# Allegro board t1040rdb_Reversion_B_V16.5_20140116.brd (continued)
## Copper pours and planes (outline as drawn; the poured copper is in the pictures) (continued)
(no net) on TOP: 52.7,56.13 52.45,56.39 52.45,60.32 50.93,61.85 50.93,75.18 50.29,75.82 40.77,75.82 40.39,76.2 40.39,79.76 39.88,80.26 37.08,80.26 36.58,79.76 36.58,76.2 35.56,75.18 30.1,75.18 29.84,75.44 29.84,77.6 30.61,78.36 32.38,78.36 35.31,81.28 53.47,81.28 53.98,80.77 53.98,80.01 54.61,79.38 54.61,77.98 55.37,77.22 58.17,77.22 59.56,75.82 61.21,75.82 61.47,76.07 61.47,78.74 61.59,78.87 64.01,78.87 64.77,78.11 67.31,78.11 67.95,78.74 67.95,82.17 67.44,82.68 64.77,82.68 64.39,83.06 64.39,83.82 63.88,84.33 63.5,84.33 63.37,84.45 63.37,85.34 63.5,85.47 68.96,85.47 69.98,84.45 69.98,74.93 69.09,74.04 55.88,74.04 55.37,73.53 55.37,62.1 57.02,60.45 57.02,56.39 56.77,56.13
(no net) on TOP: 205.49,131.83 208.03,131.83 208.41,132.21 208.41,140.21 208.03,140.59 204.98,140.59 202.95,138.56 202.95,133.86 203.2,133.6 204.72,133.6 205.1,133.22 205.1,132.21
(no net) on TOP: 29.72,110.36 27.43,110.36 26.8,111 24,111 23.88,111.12 23.88,112.52 24,112.65 26.67,112.65 27.94,113.92 29.72,113.92 29.97,113.67 29.97,110.62
(no net) on TOP: 70.48,85.09 70.48,77.09 70.87,76.71 75.57,76.71 75.95,77.09 75.95,80.77 75.69,81.03 75.31,81.03 74.99,81.34 74.99,82.55 74.04,83.5 74.04,86.36 73.79,86.61 72.01,86.61
(no net) on BOTTOM: 23.11,99.57 22.48,99.57 22.35,99.7 22.35,100.33 22.1,100.58 21.59,100.58 21.46,100.71 21.46,103 21.59,103.12 22.99,103.12 23.24,102.87 23.24,99.7
(no net) on BOTTOM: 73.79,76.33 73.79,84.96 73.15,85.6 71.12,85.6 70.87,85.34 70.87,76.33 71.12,76.07 73.53,76.07
(no net) on BOTTOM: 218.31,138.68 218.95,138.68 219.07,138.56 219.07,137.92 219.33,137.67 219.84,137.67 219.96,137.54 219.96,135.25 219.84,135.13 218.44,135.13 218.19,135.38 218.19,138.56
(no net) on BOTTOM: 187.45,74.17 187.71,74.42 187.71,83.82 187.45,84.07 185.29,84.07 183.26,82.04 183.26,74.68 183.77,74.17
(no net) on BOTTOM: 60.58,78.61 59.94,78.61 59.82,78.74 59.82,79.38 59.56,79.63 59.05,79.63 58.93,79.76 58.93,82.04 59.05,82.17 60.45,82.17 60.71,81.92 60.71,78.74
(no net) on BOTTOM: 23.11,88.77 22.48,88.77 22.35,88.9 22.35,89.54 22.1,89.79 21.59,89.79 21.46,89.92 21.46,92.2 21.59,92.33 22.99,92.33 23.24,92.08 23.24,88.9
(no net) on BOTTOM: 61.21,82.17 61.21,81.28 61.47,81.03 65.28,81.03 65.53,81.28 65.53,84.33 64.39,85.47 61.47,85.47 61.09,85.85 59.18,85.85 58.93,85.6 58.93,83.06 59.31,82.68 60.71,82.68
(no net) on BOTTOM: 36.32,108.08 36.32,117.48 36.07,117.73 33.66,117.73 33.4,117.48 33.4,108.08 33.66,107.82 36.07,107.82
(no net) on BOTTOM: 23.75,113.92 23.75,113.03 24,112.78 27.81,112.78 28.07,113.03 28.07,116.08 26.92,117.22 24,117.22 23.62,117.6 21.72,117.6 21.46,117.35 21.46,114.81 21.84,114.43 23.24,114.43
(no net) on BOTTOM: 197.99,81.53 198.63,81.53 198.75,81.41 198.75,80.77 199.01,80.52 199.52,80.52 199.64,80.39 199.64,78.11 199.52,77.98 198.12,77.98 197.87,78.23 197.87,81.41
(no net) on BOTTOM: 188.47,74.17 188.21,74.42 188.21,86.74 188.72,87.25 188.72,92.46 189.36,93.09 195.71,93.09 197.29,91.5 197.29,85.28 197.23,85.22 197.23,80.14 196.72,79.63 193.04,79.63 192.53,79.12 192.53,74.42 192.28,74.17
(no net) on BOTTOM: 23.11,110.36 22.48,110.36 22.35,110.49 22.35,111.12 22.1,111.38 21.59,111.38 21.46,111.51 21.46,113.79 21.59,113.92 22.99,113.92 23.24,113.67 23.24,110.49
(no net) on BOTTOM: 197.1,74.68 194.18,74.68 193.04,75.82 193.04,78.87 193.29,79.12 197.1,79.12 197.36,78.87 197.36,77.98 197.87,77.47 199.26,77.47 199.64,77.09 199.64,76.96 200.91,76.96 203.71,74.17 208.28,74.17 213.87,79.76 213.87,90.93 214.25,91.31 222.12,91.31 227.84,87.26 227.84,78.74 225.17,76.07 216.03,76.07 211.96,72.01 199.77,72.01 ; 1 cut-out
(no net) on BOTTOM: 36.32,97.28 36.32,106.68 36.07,106.93 33.66,106.93 33.4,106.68 33.4,97.28 33.66,97.03 36.07,97.03
(no net) on BOTTOM: 24.38,86.23 23.88,86.74 23.88,90.17 24.38,90.68 28.07,90.68 28.58,91.19 28.58,95.12 27.3,96.39 24.38,96.39 23.88,96.9 23.88,100.97 24.38,101.47 28.07,101.47 28.58,101.98 28.58,105.92 27.3,107.19 24.26,107.19 23.88,107.57 23.88,111.76 24.38,112.27 28.07,112.27 28.58,112.78 28.58,117.48 28.83,117.73 32.64,117.73 32.89,117.48 32.89,86.49 32.64,86.23
(no net) on BOTTOM: 23.75,103.12 23.75,102.23 24,101.98 27.81,101.98 28.07,102.23 28.07,105.28 26.92,106.43 24,106.43 23.62,106.81 21.72,106.81 21.46,106.55 21.46,104.01 21.84,103.63 23.24,103.63
(no net) on BOTTOM: 70.36,85.73 70.36,76.33 70.1,76.07 61.85,76.07 61.34,76.58 61.34,80.01 61.85,80.52 65.53,80.52 66.04,81.03 66.04,85.73 66.29,85.98 70.1,85.98
(no net) on BOTTOM: 36.32,86.49 36.32,95.89 36.07,96.14 33.66,96.14 33.4,95.89 33.4,86.49 33.66,86.23 36.07,86.23
(no net) on BOTTOM: 205.1,140.97 205.1,131.57 205.36,131.32 207.77,131.32 208.03,131.57 208.03,140.97 207.77,141.22 205.36,141.22
(no net) on BOTTOM: 23.75,92.33 23.75,91.44 24,91.19 27.81,91.19 28.07,91.44 28.07,94.87 27.3,95.63 24,95.63 23.62,96.01 21.72,96.01 21.46,95.76 21.46,93.22 21.84,92.84 23.24,92.84
EARTH on TOP (solid shape): outline of 254 points within 122.52,6.52 131.52,15.52
EARTH on TOP (solid shape): outline of 254 points within 270.52,6.52 279.52,15.52
EARTH on BOTTOM (solid shape): outline of 254 points within 122.52,6.52 131.52,15.52
EARTH on BOTTOM (solid shape): outline of 254 points within 270.52,6.52 279.52,15.52
EARTH on TOP: outline of 101 points within 59.94,1.78 280.25,46.23
EARTH on BOTTOM: outline of 107 points within 59.69,1.78 280.25,46.23
EARTH on L2GND, L5PWR, L7GND: outline of 153 points within 59.94,1.78 280.25,46.1
EARTH on L4PWR: outline of 157 points within 59.94,1.78 280.25,46.1
EVDD on L4PWR: 107.04,94.62 95.61,106.05 74.91,106.05 54.72,126.24 51.79,126.24 51.56,126.47 51.56,127.66 51.67,127.76 57.04,127.76 76.09,108.71 97.94,108.71 107.97,98.68 156.49,98.68 158.9,96.27 160.38,96.27 160.91,96.8 160.91,97.9 157.72,101.08 157.72,104.15 161.92,108.35 161.92,108.46 163.14,108.46 163.19,108.41 163.19,108.15 163.4,107.95 163.45,107.95 163.45,104.29 163.96,103.78 163.96,95.86 162.71,94.62
MVREF on TOP: 225.68,145.03 226.06,145.41 226.31,145.41 226.44,145.29 226.44,144.53 226.06,144.14 222.88,144.14 222.76,144.27 222.76,144.91 222.88,145.03
OVDD on TOP: 77.85,105.79 77.85,104.01 77.98,103.89 79.76,103.89 79.88,104.01 79.88,104.52 80.77,105.41 80.77,106.17 80.65,106.3 78.36,106.3
OVDD on TOP: 59.18,118.24 59.31,118.11 61.21,118.11 62.1,119 62.1,123.95 61.85,124.21 59.82,124.21 59.18,123.57
OVDD on BOTTOM: 87.38,139.19 87.38,138.3 87.63,138.05 106.05,138.05 106.3,138.3 106.3,139.19 106.05,139.45 87.63,139.45
OVDD on L3SIG: 149.48,96.65 150.5,95.63 153.54,95.63 153.8,95.89 153.8,103.25 153.29,103.76 149.86,103.76 149.48,103.38
OVDD on L4PWR: 150.09,102.87 149.61,103.36 149.61,105.94 151.74,108.08 155.32,108.08 156.59,109.35 163.07,109.35 163.7,108.71 163.83,108.71 163.96,108.59 163.96,108.26 163.9,108.2 163.58,108.2 163.45,108.33 163.45,108.51 163.25,108.71 161.57,108.71 155.72,102.87
OVDD on L5PWR: 164.08,89.03 164.72,89.66 164.72,94.62 163.7,95.63 158.37,95.63 157.48,96.52 151.76,96.52 151.38,96.14 151.38,89.28 151.64,89.03
OVDD on L5PWR: 154.3,113.28 159.89,113.28 160.15,113.03 161.54,113.03 161.67,113.16 161.67,118.49 161.29,118.87 151.13,118.87 136.4,133.6 125.09,133.6 112.01,146.69 67.69,146.69 66.99,145.99 66.99,137.35 60.32,130.68 60.32,119.25 61.21,118.36 73.66,118.36 77.85,114.17 77.85,102.87 78.74,101.98 153.16,101.98 153.67,102.49 153.67,112.65
OVDD_OSC_DDR on TOP: 84.96,109.98 84.84,110.11 81.92,110.11 79.5,107.7 79.5,106.93 79.76,106.68 84.71,106.68 84.96,106.93
OVDD_OSC_SYS on TOP: 78.87,100.33 78.87,98.81 79.25,98.43 83.19,98.43 83.44,98.68 83.44,100.71 83.31,100.84 81.28,100.84 81.03,100.58 79.12,100.58
OVDD_OSC_USB on TOP: 80.14,93.09 80.14,91.44 79.5,90.81 79.5,90.04 79.63,89.92 83.19,89.92 83.44,90.17 83.44,92.96 83.19,93.22 80.26,93.22
OVDD_SLP on TOP: 54.48,136.65 54.61,136.52 57.02,136.52 57.15,136.65 57.15,141.48 56.77,141.86 54.61,141.86 54.48,141.73
OVDD_SLP on TOP: 77.85,87.38 79.63,87.38 79.76,87.5 79.76,88.01 80.01,88.27 80.52,88.27 80.65,88.39 80.65,89.28 80.52,89.41 77.98,89.41 77.72,89.15 77.72,87.5
OVDD_SLP on TOP: 77.34,97.03 77.47,96.9 79.12,96.9 79.5,96.52 80.52,96.52 80.77,96.77 80.77,97.66 80.52,97.92 79.12,97.92 78.11,98.93 77.6,98.93 77.47,98.81 77.47,98.3 77.34,98.17
OVDD_SLP on L3SIG: 75.95,96.52 75.95,88.9 76.45,88.39 81.41,88.39 85.73,92.71 85.73,109.73 87.63,111.63 111.51,111.63 113.67,109.47 113.67,98.3 114.81,97.16 148.08,97.16 148.97,98.04 148.97,103.63 149.61,104.27 153.54,104.27 154.3,103.51 154.3,97.03 154.56,96.77 155.83,96.77 156.59,97.54 156.59,105.41 157.1,105.92 157.1,106.17 158.11,107.19 162.43,107.19 162.69,107.44 162.69,112.52 162.31,112.9 160.27,112.9 159.89,112.52 159.89,110.36 159.38,109.86 154.69,109.86 153.29,111.25 153.29,112.9 151,115.19 151,116.97 150.62,117.35 147.57,117.35 144.91,114.68 144.91,105.28 144.4,104.78 143.51,104.78 142.88,105.41 142.88,114.43 136.78,120.52 73.66,120.52 70.36,117.22 70.36,113.92 70.87,113.41 70.87,111.38 70.48,111 67.69,111 67.06,111.63 67.06,120.78 61.79,126.05 61.79,140.02 61.21,140.59 54.61,140.59 54.23,140.21 54.23,118.24
OVDD_SLP on L5PWR: 160.91,110.62 161.42,110.62 161.54,110.74 161.54,112.65 161.42,112.78 160.91,112.78 160.78,112.65 160.78,110.74
USB1_VBUS on TOP: 65.66,19.05 65.66,17.4 66.42,16.64 66.42,13.97 64.77,12.32 64.77,11.68 65.15,11.3 66.04,11.3 67.18,12.45 67.18,19.05 67.06,19.18 65.79,19.18
USB2_VBUS on TOP: 63.75,19.18 65.02,19.18 65.15,19.05 65.15,17.53 66.17,16.51 66.17,14.35 65.91,14.1 65.02,14.1 64.77,14.35 64.77,16.13 63.63,17.27 63.63,19.05
VBH on TOP: 29.84,74.3 29.84,71.12 30.35,70.61 37.85,70.61 39.12,71.88 39.12,75.31 38.86,75.57 37.08,75.57 36.07,74.55 30.1,74.55
VBH1 on TOP: 50.04,50.93 52.58,50.93 53.34,50.16 56.13,50.16 56.39,49.91 56.39,48.51 56.13,48.26 50.04,48.26 49.78,48.51 49.78,50.67
VBH2 on TOP: 48.26,54.99 48.26,48.51 48.01,48.26 34.42,48.26 29.59,53.09 29.59,67.82 30.48,68.71 36.07,68.71 37.08,67.69 37.08,57.53 38.86,55.75 47.5,55.75
VBL1 on TOP: 56.39,53.72 56.13,53.47 53.34,53.47 52.2,52.32 49.15,52.32 48.89,52.58 48.89,54.99 49.15,55.24 56.13,55.24 56.39,54.99
VBL2 on TOP: 51.43,56.52 51.69,56.77 51.69,59.94 50.04,61.59 50.04,74.93 49.78,75.18 47.62,75.18 46.23,73.79 46.23,69.47 45.47,68.71 39.12,68.71 37.97,67.56 37.97,57.66 39.12,56.52
VCORE on TOP: 133.48,104.01 132.21,105.28 130.81,105.28 130.43,105.66 130.43,109.22 130.81,109.6 131.95,109.6 132.33,109.98 132.33,115.06 132.46,115.19 134.75,115.19 136.02,113.92 136.02,104.14 135.89,104.01
VCORE on BOTTOM: 139.7,105.28 139.83,105.16 142.11,105.16 142.24,105.28 142.24,109.09 142.11,109.22 139.83,109.22 139.7,109.09
VCORE on BOTTOM: 135.76,103.51 136.02,103.76 136.02,115.19 135.76,115.44 131.19,115.44 130.94,115.19 130.94,103.76 131.19,103.51
VCORE on L3SIG: 159.89,114.3 160.15,114.55 162.43,114.55 162.56,114.68 162.56,115.06 162.69,115.19 163.07,115.19 163.19,115.32 163.19,115.82 162.94,116.08 160.27,116.08 159.89,115.7 158.24,115.7 157.86,116.08 156.08,116.08 155.7,115.7 155.7,114.55 155.96,114.3
VCORE on L4PWR: 133.33,103.51 132.08,104.75 132.08,118.39 132.69,119 158.98,119 159.11,119.13 169.19,119.13 169.31,119 169.49,119 169.67,118.82 169.67,114.37 170.43,113.61 170.43,112.22 170.76,111.89 172.03,111.89 172.21,111.71 172.21,108.33 171.96,108.08 170.74,108.08 170.56,108.26 170.56,108.64 170.23,108.97 163.83,108.97 163.19,109.6 156.46,109.6 155.45,108.59 151.53,108.59 149.1,106.15 149.1,103.76 148.84,103.51
VCORE on L5PWR: 161.92,119 161.92,113.16 170.31,113.16 170.81,112.65 170.81,108.08 170.94,107.95 171.83,107.95 172.21,108.33 172.21,114.05 171.96,114.3 169.93,114.3 169.67,114.55 169.67,119
VCORE_SLP on TOP: 119.76,90.55 120.14,90.17 127,90.17 127.38,90.55 127.38,104.14 126.87,104.65 124.21,104.65 123.57,105.28 123.57,108.2 123.32,108.46 120.14,108.46 119.76,108.08
VCORE_SLP on BOTTOM: 136.27,95.5 138.68,95.5 138.94,95.76 138.94,101.09 138.68,101.35 136.27,101.35 136.02,101.09 136.02,95.76
VCORE_SLP on BOTTOM: 130.17,90.17 130.43,90.42 130.43,115.06 130.05,115.44 123.95,115.44 123.7,115.19 123.7,109.47 123.19,108.97 120.4,108.97 119.89,108.46 119.89,90.42 120.14,90.17
VCORE_SLP on L5PWR: 161.8,112.65 161.8,110.74 161.92,110.62 163.58,110.62 164.59,109.6 164.59,107.32 163.19,105.92 163.19,101.73 162.81,101.35 119.13,101.35 118.49,100.71 118.49,90.81 120.02,89.28 143.89,89.28 151.64,97.03 157.73,97.03 158.62,96.14 168.66,96.14 170.56,98.04 170.56,112.65 170.31,112.9 162.05,112.9
VCORE_SLP on L6SIG: 119.89,108.97 119.89,89.28 120.4,88.77 126.87,88.77 127.38,89.28 127.38,108.97 126.87,109.47 120.4,109.47
VCORE_SW1 on TOP: 110.11,90.93 110.24,90.81 114.81,90.81 115.19,91.19 115.19,97.28 114.81,97.66 110.36,97.66 110.11,97.41
VCORE_SW2 on TOP: 110.11,101.09 110.24,100.97 114.81,100.97 115.19,101.35 115.19,107.82 114.81,108.2 110.36,108.2 110.11,107.95
VTT on TOP: 148.34,164.97 149.86,164.97 150.37,165.48 150.37,165.73 150.62,165.99 151.51,165.99 151.64,165.86 151.64,164.08 151.26,163.7 148.46,163.7 148.21,163.96 148.21,164.85
VTT on TOP: 226.31,150.5 226.69,150.11 226.69,149.61 227.2,149.1 227.2,148.72 227.46,148.72 227.46,149.1 227.97,149.61 227.97,160.02 227.58,160.4 226.31,160.4 226.06,160.15 226.06,158.62 226.69,157.99 226.69,157.1 226.06,156.46 226.06,154.56 226.31,154.3
VTT on BOTTOM: 156.84,156.84 156.84,161.67 157.48,162.31 225.3,162.31 225.93,161.67 225.93,158.75 226.69,157.99 226.69,157.1 225.93,156.34 225.93,155.07 226.19,154.81 227.46,154.81 228.35,155.7 228.35,162.81 226.44,164.72 148.84,164.72 148.34,164.21 148.34,162.18 148.72,161.8 148.72,156.97 149.73,155.96 149.73,155.19 150.37,154.56 154.56,154.56
XVDD on TOP: 193.93,129.92 193.93,127.38 196.09,127.38 196.34,127.64 196.34,129.67 196.09,129.92
XVDD on L4PWR: 172.47,108.46 172.47,111.78 172.72,112.04 172.72,119.63 172.97,119.89 177.65,119.89 187.94,130.17 195.96,130.17 196.22,129.92 196.22,123.17 181.25,108.2 172.72,108.2
XVDD on L5PWR: 174.37,119.76 172.97,119.76 172.72,119.51 172.72,108.97 172.97,108.71 174.37,108.71 174.62,108.97 174.62,119.51
N16851789 on TOP: 66.93,73.03 67.06,72.9 67.06,60.58 70.1,57.53 72.77,57.53 72.77,56.13 70.1,56.13 69.34,55.37 59.82,55.37 58.93,56.26 58.93,71.63 60.32,73.03
N16851789 on BOTTOM: 63.5,54.23 64.77,54.23 65.02,54.48 65.02,55.75 64.77,56.01 63.5,56.01 63.25,55.75 63.25,54.48
N16851797 on TOP: 72.64,69.34 72.9,69.6 72.9,71.63 72.64,71.88 68.45,71.88 68.2,71.63 68.2,69.6 68.45,69.34
N16851797 on BOTTOM: 67.82,71.5 67.82,69.47 68.07,69.22 70.87,69.22 71.12,69.47 71.12,71.63 70.87,71.88 68.2,71.88
N16852263 on BOTTOM: 63.5,50.93 72.39,50.93 72.64,51.18 72.64,53.47 72.39,53.72 63.5,53.72 63.25,53.47 63.25,51.18
N16879465 on TOP: 153.54,47.12 154.56,47.12 155.19,47.75 155.7,47.75 155.7,45.97 154.81,45.09 153.54,45.09 153.42,45.21 153.42,46.99
N16909680 on TOP: 186.05,60.96 186.69,60.96 186.69,59.69 186.44,59.44 186.44,57.15 185.93,56.64 184.66,56.64 184.4,56.9 184.4,59.18 184.53,59.31 184.53,59.69 184.66,59.82 185.17,59.82 185.93,60.58 185.93,60.83
N16973728 on TOP: 131.32,47.75 132.33,47.75 132.97,48.39 133.48,48.39 133.48,46.61 132.59,45.72 131.32,45.72 131.19,45.85 131.19,47.62
N17021052 on TOP: 74.3,17.91 74.3,19.05 74.17,19.18 72.77,19.18 71.76,18.16 71.76,14.35 72.01,14.1 72.9,14.1 73.15,14.35 73.15,16.76
N17021059 on BOTTOM: 73.15,11.3 73.53,11.68 73.53,16.13 74.3,16.89 74.3,19.05 74.17,19.18 72.52,19.18 71.12,17.78 71.12,11.81 71.63,11.3
N17257020 on TOP: 70.23,54.99 70.23,51.18 72.77,51.18 72.77,54.99
N17403382 on TOP: 59.94,134.75 61.34,134.75 61.72,134.37 63.63,134.37 64.9,135.64 66.8,135.64 67.18,135.25 67.18,134.49 66.68,133.98 65.53,133.98 63.25,131.7 63.25,129.03 62.61,128.4 61.21,128.4 60.58,129.03 60.58,132.72 59.69,133.6 59.69,134.49
N17403388 on TOP: 64.52,138.3 64.52,137.29 63.63,136.4 61.85,136.4 61.34,136.91 61.34,137.67 61.09,137.92 58.04,137.92 57.66,137.54 57.66,135.76 57.78,135.64 58.55,135.64 58.8,135.38 61.59,135.38 61.85,135.13 63.5,135.13 64.52,136.14 67.06,136.14 67.82,135.38 67.82,133.98 66.93,133.1 66.29,133.1 65.91,132.72 65.91,132.08 66.29,131.7 67.44,131.7 68.83,133.1 68.83,135.76 66.93,137.67 66.93,138.05 66.42,138.56 64.77,138.56
N17523733 on TOP: 57.4,135 58.42,135 58.67,134.75 58.67,129.16 58.42,128.91 57.66,128.91 57.28,129.29 57.28,133.1 56.52,133.86 54.36,133.86 54.1,134.11 54.1,135.25 54.36,135.51 56.9,135.51
N18564847 on TOP: 43.94,122.94 43.69,123.19 43.69,125.98 42.16,127.51 42.16,130.3 42.55,130.68 44.32,130.68 44.58,130.43 44.58,127.76 45.97,126.37 45.97,123.19 45.72,122.94
N19644915 on TOP (solid shape): 214.63,138.05 217.42,138.05 217.55,137.92 217.55,136.52 217.42,136.4 214.76,136.4 213.49,135.13 211.71,135.13 211.45,135.38 211.45,138.43 211.71,138.68 214,138.68
N19646811 on TOP (solid shape): 29.97,102.87 29.97,99.82 29.72,99.57 27.43,99.57 26.8,100.2 24,100.2 23.88,100.33 23.88,101.73 24,101.85 26.67,101.85 27.94,103.12 29.72,103.12
N19648273 on TOP (solid shape): 29.97,92.08 29.97,89.03 29.72,88.77 27.43,88.77 26.8,89.41 24,89.41 23.88,89.54 23.88,90.93 24,91.06 26.67,91.06 27.94,92.33 29.72,92.33
N19650144 on TOP (solid shape): 67.44,81.92 67.44,78.87 67.18,78.61 64.9,78.61 64.26,79.25 61.47,79.25 61.34,79.38 61.34,80.77 61.47,80.9 64.14,80.9 65.41,82.17 67.18,82.17
N19651609 on TOP (solid shape): 29.97,113.67 29.97,110.62 29.72,110.36 27.43,110.36 26.8,111 24,111 23.88,111.12 23.88,112.52 24,112.65 26.67,112.65 27.94,113.92 29.72,113.92
N19653096 on TOP (solid shape): 194.31,80.9 197.1,80.9 197.23,80.77 197.23,79.38 197.1,79.25 194.44,79.25 193.17,77.98 191.39,77.98 191.13,78.23 191.13,81.28 191.39,81.53 193.67,81.53
N22787926 on TOP: 48.51,130.43 48.77,130.68 50.42,130.68 50.93,130.17 50.93,123.19 50.67,122.94 49.02,122.94 48.77,123.19 48.77,126.87 48.51,127.13

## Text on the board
Ref Des/Silkscreen Top: ON/OFF | CPLD_PROG | COP | RESET | SYS_FAN1 | T1040 | T2081 | PROG_SFP | FA_VDD | PROG_MTR | OFF <-> ON | VDD_LP_DET | FULL_SPEED | PROG_VCORE | ASLEEP | 0 | 1 | VDD_LP_BAT | SYS_FAN2 | SYS_FAN3 | DDR_PWR | OFF:1.35V | ON:1.5V | SYS_FAN4 | CPU_FAN
NCLEGEND-1-8: FIGURE | SIZE | 10.0 | 16.0 | 19.69 | 27.56 | 29.13 | 33.46 | 35.04 | 35.43 | 37.4 | 39.37 | 41.34 | 43.31 | 51.18 | 53.15 | 55.12 | 62.99 | 90.55 | 106.3 | 133.86 | 59.06 | 61.02 | 92.52 | 94.49 | 96.46 | 125.98 | 127.95 | 157.48 | DRILL CHART: TOP to BOTTOM | ALL UNITS ARE IN MILS | PLATED | NON-PLATED | QTY | 3559 | 218 | 64 | 304 | 7 | 1 | 4 | 151 | 9 | 59 | 10 | 40 | 2 | 20 | 16 | 3 | 12 | 8
